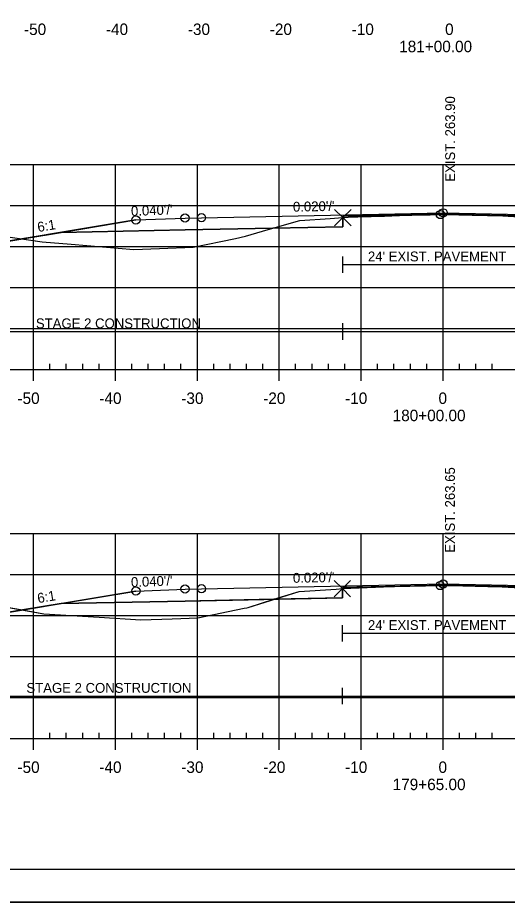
# Model space of a CAD drawing. Extents: x 1365647 to 1367999, y 387113 to 400173.
# Drawn here: x 1365842.2 to 1365901.9, y 388012.7 to 388120.6 of the extents above; entities that cross this region are included whole.
import ezdxf

# ---------------------------------------------------------------- set-up
doc = ezdxf.new("R2010")
doc.units = 0
for name, color, linetype in [('R_Alt Surface', 7, 'Continuous'), ('R_Axis', 7, 'Continuous'), ('R_Axis Annot', 7, 'Continuous'), ('R_Border', 7, 'Continuous'), ('R_Contours', 7, 'Continuous'), ('R_Exist Surface', 7, 'Continuous'), ('R_Fin Surface', 7, 'Continuous'), ('R_Fin Surface Annot', 7, 'Continuous'), ('R_Grid', 7, 'Continuous'), ('R_No Plot', 7, 'Continuous'), ('R_Proposed Const Limits', 7, 'Continuous'), ('R_Water', 7, 'Continuous'), ('R_Xsect Elev', 7, 'Continuous')]:
    doc.layers.add(name, color=color, linetype=linetype)

msp = doc.modelspace()

# ---------------------------------------------------------------- linework, layer by layer
at = {"layer": 'R_Alt Surface'}
for points in [[(1365847.47, 388094.45), (1365862.59, 388094.76), (1365881.85, 388095.14), (1365881.85, 388096.43), (1365894.09, 388096.67), (1365905.63, 388096.44), (1365905.63, 388095.16), (1365925.59, 388094.76), (1365940.72, 388094.45)], [(1365847.47, 388049.19), (1365862.59, 388049.49), (1365881.8, 388049.88), (1365881.8, 388051.16), (1365894.09, 388051.41), (1365905.6, 388051.18), (1365905.6, 388049.89), (1365925.59, 388049.49), (1365940.72, 388049.19)]]:
    msp.add_lwpolyline(points, dxfattribs=at)
at = {"layer": 'R_Axis'}
for p, q in [((1365749.09, 388077.73), (1366039.09, 388077.73)), ((1365844.09, 388076.33), (1365844.09, 388077.73)), ((1365846.09, 388077.73), (1365846.09, 388078.43)), ((1365848.09, 388077.73), (1365848.09, 388078.43)), ((1365850.09, 388077.73), (1365850.09, 388078.43)), ((1365852.09, 388077.73), (1365852.09, 388078.43)), ((1365854.09, 388076.33), (1365854.09, 388077.73)), ((1365856.09, 388077.73), (1365856.09, 388078.43)), ((1365858.09, 388077.73), (1365858.09, 388078.43)), ((1365860.09, 388077.73), (1365860.09, 388078.43)), ((1365862.09, 388077.73), (1365862.09, 388078.43)), ((1365864.09, 388076.33), (1365864.09, 388077.73)), ((1365866.09, 388077.73), (1365866.09, 388078.43)), ((1365868.09, 388077.73), (1365868.09, 388078.43)), ((1365870.09, 388077.73), (1365870.09, 388078.43)), ((1365872.09, 388077.73), (1365872.09, 388078.43)), ((1365874.09, 388076.33), (1365874.09, 388077.73)), ((1365876.09, 388077.73), (1365876.09, 388078.43)), ((1365878.09, 388077.73), (1365878.09, 388078.43)), ((1365880.09, 388077.73), (1365880.09, 388078.43)), ((1365882.09, 388077.73), (1365882.09, 388078.43)), ((1365884.09, 388076.33), (1365884.09, 388077.73)), ((1365886.09, 388077.73), (1365886.09, 388078.43)), ((1365888.09, 388077.73), (1365888.09, 388078.43)), ((1365890.09, 388077.73), (1365890.09, 388078.43)), ((1365892.09, 388077.73), (1365892.09, 388078.43)), ((1365894.09, 388076.33), (1365894.09, 388077.73)), ((1365896.09, 388077.73), (1365896.09, 388078.43)), ((1365898.09, 388077.73), (1365898.09, 388078.43)), ((1365900.09, 388077.73), (1365900.09, 388078.43)), ((1365846.09, 388032.73), (1365846.09, 388033.43)), ((1365848.09, 388032.73), (1365848.09, 388033.43)), ((1365850.09, 388032.73), (1365850.09, 388033.43)), ((1365852.09, 388032.73), (1365852.09, 388033.43)), ((1365856.09, 388032.73), (1365856.09, 388033.43)), ((1365858.09, 388032.73), (1365858.09, 388033.43)), ((1365860.09, 388032.73), (1365860.09, 388033.43)), ((1365862.09, 388032.73), (1365862.09, 388033.43)), ((1365866.09, 388032.73), (1365866.09, 388033.43)), ((1365868.09, 388032.73), (1365868.09, 388033.43)), ((1365870.09, 388032.73), (1365870.09, 388033.43)), ((1365872.09, 388032.73), (1365872.09, 388033.43)), ((1365876.09, 388032.73), (1365876.09, 388033.43)), ((1365878.09, 388032.73), (1365878.09, 388033.43)), ((1365880.09, 388032.73), (1365880.09, 388033.43)), ((1365882.09, 388032.73), (1365882.09, 388033.43)), ((1365886.09, 388032.73), (1365886.09, 388033.43)), ((1365888.09, 388032.73), (1365888.09, 388033.43)), ((1365890.09, 388032.73), (1365890.09, 388033.43)), ((1365892.09, 388032.73), (1365892.09, 388033.43)), ((1365896.09, 388032.73), (1365896.09, 388033.43)), ((1365898.09, 388032.73), (1365898.09, 388033.43)), ((1365900.09, 388032.73), (1365900.09, 388033.43)), ((1365749.09, 388032.73), (1366039.09, 388032.73)), ((1365844.09, 388031.33), (1365844.09, 388032.73)), ((1365854.09, 388031.33), (1365854.09, 388032.73)), ((1365864.09, 388031.33), (1365864.09, 388032.73)), ((1365874.09, 388031.33), (1365874.09, 388032.73)), ((1365884.09, 388031.33), (1365884.09, 388032.73)), ((1365894.09, 388031.33), (1365894.09, 388032.73))]:
    msp.add_line(p, q, dxfattribs=at)
at = {"layer": 'R_Border'}
msp.add_line((1366052.27, 388016.73), (1365736.09, 388016.73), dxfattribs=at)
at = {"layer": 'R_Contours'}
for points in [[(1365873.31, 388094.97), (1365876.58, 388095.9), (1365880.31, 388096.15), (1365881.85, 388096.26), (1365881.85, 388095.14)], [(1365881.85, 388096.26), (1365882.05, 388096.27), (1365882.5, 388096.3), (1365883.7, 388096.34), (1365886.94, 388096.45), (1365888.78, 388096.51), (1365890.29, 388096.54), (1365892.53, 388096.6), (1365893.75, 388096.63), (1365894, 388096.63), (1365894.4, 388096.65), (1365897.62, 388096.57), (1365901.4, 388096.47), (1365903.39, 388096.37), (1365905.63, 388096.26), (1365905.63, 388096.44), (1365894.09, 388096.67), (1365881.85, 388096.43)], [(1365826.79, 388094.91), (1365834.26, 388094.87), (1365839.81, 388094.08), (1365842.68, 388093.66), (1365834.59, 388092.31)], [(1365842.68, 388093.66), (1365845.15, 388093.29), (1365848.67, 388093.01), (1365856.34, 388092.36), (1365859.45, 388092.49), (1365863.56, 388092.65), (1365868.75, 388093.73), (1365869.97, 388093.98), (1365872.74, 388094.81), (1365873.31, 388094.97), (1365862.59, 388094.76), (1365847.47, 388094.45)], [(1365873.44, 388049.71), (1365876.51, 388050.67), (1365881.04, 388050.96), (1365881.8, 388051.01), (1365881.8, 388049.88)], [(1365881.8, 388051.01), (1365881.85, 388051.01), (1365886.83, 388051.21), (1365888.15, 388051.26), (1365891.96, 388051.36), (1365892.91, 388051.38), (1365893.59, 388051.38), (1365893.73, 388051.38), (1365893.92, 388051.38), (1365894.99, 388051.38), (1365898, 388051.29), (1365899.57, 388051.25), (1365901.32, 388051.22), (1365904.17, 388051.05), (1365904.79, 388051.02), (1365905.54, 388050.99), (1365905.6, 388050.98), (1365905.6, 388051.18), (1365894.09, 388051.41), (1365881.8, 388051.16)], [(1365826.18, 388049.85), (1365835.06, 388049.84), (1365838.94, 388049.08), (1365842.76, 388048.41), (1365834.59, 388047.04)], [(1365842.76, 388048.41), (1365845.34, 388047.95), (1365852.12, 388047.54), (1365857.19, 388047.21), (1365861.02, 388047.34), (1365864.15, 388047.43), (1365869.82, 388048.61), (1365870.13, 388048.67), (1365870.28, 388048.72), (1365873.44, 388049.71), (1365862.59, 388049.49), (1365847.47, 388049.19)]]:
    msp.add_lwpolyline(points, close=True, dxfattribs=at)
at = {"layer": 'R_Exist Surface'}
for points in [[(1365839.81, 388094.08), (1365845.15, 388093.29), (1365848.67, 388093.01), (1365856.34, 388092.36), (1365859.45, 388092.49), (1365863.56, 388092.65), (1365868.75, 388093.73), (1365869.97, 388093.98), (1365872.74, 388094.81), (1365876.58, 388095.9), (1365880.31, 388096.15), (1365881.85, 388096.26), (1365882.05, 388096.27), (1365882.5, 388096.3), (1365883.7, 388096.34), (1365886.94, 388096.45), (1365888.78, 388096.51), (1365890.29, 388096.54), (1365892.53, 388096.6), (1365893.75, 388096.63), (1365894, 388096.63), (1365894.4, 388096.65), (1365897.62, 388096.57), (1365901.4, 388096.47), (1365903.39, 388096.37)], [(1365838.94, 388049.08), (1365845.34, 388047.95), (1365852.12, 388047.54), (1365857.19, 388047.21), (1365861.02, 388047.34), (1365864.15, 388047.43), (1365869.82, 388048.61), (1365870.13, 388048.67), (1365870.28, 388048.72), (1365876.51, 388050.67), (1365881.04, 388050.96), (1365881.8, 388051.01), (1365881.85, 388051.01), (1365886.83, 388051.21), (1365888.15, 388051.26), (1365891.96, 388051.36), (1365892.91, 388051.38), (1365893.59, 388051.38), (1365893.73, 388051.38), (1365893.92, 388051.38), (1365894.99, 388051.38), (1365898, 388051.29), (1365899.57, 388051.25), (1365901.32, 388051.22), (1365904.17, 388051.05)]]:
    msp.add_lwpolyline(points, dxfattribs=at)
at = {"layer": 'R_Fin Surface'}
for points in [[(1365826.79, 388094.91), (1365834.59, 388092.31), (1365847.47, 388094.45), (1365856.59, 388095.97), (1365862.59, 388096.21), (1365864.59, 388096.25), (1365894.09, 388096.84), (1365923.59, 388096.25), (1365925.59, 388096.21), (1365931.59, 388095.97), (1365940.72, 388094.45), (1365953.59, 388092.31), (1365958.72, 388094.02)], [(1365856.59, 388095.97), (1365862.59, 388096.21), (1365864.59, 388096.25), (1365894.09, 388096.84), (1365923.59, 388096.25), (1365925.59, 388096.21), (1365931.59, 388095.97)], [(1365826.18, 388049.85), (1365834.59, 388047.04), (1365847.47, 388049.19), (1365856.59, 388050.71), (1365862.59, 388050.95), (1365864.59, 388050.99), (1365894.09, 388051.58), (1365923.59, 388050.99), (1365925.59, 388050.95), (1365931.59, 388050.71), (1365940.72, 388049.19), (1365953.59, 388047.04), (1365959.19, 388048.91)], [(1365856.59, 388050.71), (1365862.59, 388050.95), (1365864.59, 388050.99), (1365894.09, 388051.58), (1365923.59, 388050.99), (1365925.59, 388050.95), (1365931.59, 388050.71)]]:
    msp.add_lwpolyline(points, dxfattribs=at)
at = {"layer": 'R_Grid'}
for p, q in [((1365749.09, 388102.73), (1366039.09, 388102.73)), ((1365844.09, 388077.73), (1365844.09, 388102.73)), ((1365854.09, 388077.73), (1365854.09, 388102.73)), ((1365864.09, 388077.73), (1365864.09, 388102.73)), ((1365874.09, 388077.73), (1365874.09, 388102.73)), ((1365884.09, 388077.73), (1365884.09, 388102.73)), ((1365894.09, 388077.73), (1365894.09, 388102.73)), ((1365749.09, 388097.73), (1366039.09, 388097.73)), ((1365749.09, 388092.73), (1366039.09, 388092.73)), ((1365749.09, 388087.73), (1366039.09, 388087.73)), ((1365749.09, 388082.73), (1366039.09, 388082.73)), ((1365749.09, 388077.73), (1366039.09, 388077.73)), ((1365749.09, 388057.73), (1366039.09, 388057.73)), ((1365844.09, 388032.73), (1365844.09, 388057.73)), ((1365854.09, 388032.73), (1365854.09, 388057.73)), ((1365864.09, 388032.73), (1365864.09, 388057.73)), ((1365874.09, 388032.73), (1365874.09, 388057.73)), ((1365884.09, 388032.73), (1365884.09, 388057.73)), ((1365894.09, 388032.73), (1365894.09, 388057.73)), ((1365749.09, 388052.73), (1366039.09, 388052.73)), ((1365749.09, 388047.73), (1366039.09, 388047.73)), ((1365749.09, 388042.73), (1366039.09, 388042.73)), ((1365749.09, 388037.73), (1366039.09, 388037.73)), ((1365749.09, 388032.73), (1366039.09, 388032.73))]:
    msp.add_line(p, q, dxfattribs=at)
at = {"layer": 'R_No Plot'}
msp.add_line((1365723.69, 388012.75), (1366057.03, 388012.75), dxfattribs=at)
msp.add_lwpolyline([(1365723.69, 388226.09), (1366057.03, 388226.09), (1366057.03, 388012.75), (1365723.69, 388012.75)], close=True, dxfattribs=at)
for points in [[(1365881.85, 388096.26), (1365880.85, 388097.26), (1365881.85, 388096.26), (1365880.85, 388095.26), (1365881.85, 388096.26), (1365882.85, 388095.26), (1365881.85, 388096.26), (1365882.85, 388097.26)], [(1365881.8, 388051.01), (1365880.8, 388052.01), (1365881.8, 388051.01), (1365880.8, 388050.01), (1365881.8, 388051.01), (1365882.8, 388050.01), (1365881.8, 388051.01), (1365882.8, 388052.01)]]:
    msp.add_lwpolyline(points, dxfattribs=at)
for centre in [(1365893.75, 388096.63), (1365894.09, 388096.84), (1365894.09, 388096.84), (1365894.09, 388096.84), (1365894.09, 388096.84), (1365894.09, 388096.84), (1365856.59, 388095.97), (1365856.59, 388095.97), (1365856.59, 388095.97), (1365856.59, 388095.97), (1365856.59, 388095.97), (1365862.59, 388096.21), (1365862.59, 388096.21), (1365862.59, 388096.21), (1365862.59, 388096.21), (1365862.59, 388096.21), (1365864.59, 388096.25), (1365864.59, 388096.25), (1365864.59, 388096.25), (1365864.59, 388096.25), (1365864.59, 388096.25), (1365864.59, 388050.99), (1365864.59, 388050.99), (1365864.59, 388050.99), (1365864.59, 388050.99), (1365864.59, 388050.99), (1365893.73, 388051.38), (1365894.09, 388051.58), (1365894.09, 388051.58), (1365894.09, 388051.58), (1365894.09, 388051.58), (1365894.09, 388051.58), (1365856.59, 388050.71), (1365856.59, 388050.71), (1365856.59, 388050.71), (1365856.59, 388050.71), (1365856.59, 388050.71), (1365862.59, 388050.95), (1365862.59, 388050.95), (1365862.59, 388050.95), (1365862.59, 388050.95), (1365862.59, 388050.95)]:
    msp.add_circle(centre, 0.5, dxfattribs=at)
at = {"layer": 'R_Proposed Const Limits'}
for points in [[(1365856.59, 388095.97), (1365834.59, 388092.31), (1365826.79, 388094.91)], [(1365856.59, 388050.71), (1365834.59, 388047.04), (1365826.18, 388049.85)]]:
    msp.add_lwpolyline(points, dxfattribs=at)
at = {"layer": 'R_Water'}
for p, q in [((1365881.85, 388089.53), (1365881.85, 388091.53)), ((1365881.85, 388090.53), (1365905.63, 388090.53)), ((1365881.85, 388081.37), (1365881.85, 388083.37)), ((1365826.79, 388082.37), (1365881.85, 388082.37)), ((1365881.85, 388082.37), (1365958.72, 388082.37)), ((1365881.8, 388044.57), (1365881.8, 388046.57)), ((1365881.8, 388045.57), (1365905.6, 388045.57)), ((1365881.8, 388036.91), (1365881.8, 388038.91)), ((1365826.13, 388037.91), (1365881.8, 388037.91)), ((1365881.8, 388037.91), (1365959.19, 388037.91))]:
    msp.add_line(p, q, dxfattribs=at)

# ---------------------------------------------------------------- texts
at = {"layer": 'R_Axis Annot'}
for s, p in [('-50', (1365842.93, 388118.53)), ('-40', (1365852.93, 388118.53)), ('-30', (1365862.93, 388118.53)), ('-20', (1365872.93, 388118.53)), ('-10', (1365882.93, 388118.53)), ('0', (1365894.33, 388118.53)), ('181+00.00', (1365888.73, 388116.43)), ('-50', (1365842.13, 388073.53)), ('-40', (1365852.13, 388073.53)), ('-30', (1365862.13, 388073.53)), ('-20', (1365872.13, 388073.53)), ('-10', (1365882.13, 388073.53)), ('0', (1365893.53, 388073.53)), ('180+00.00', (1365887.93, 388071.43)), ('-50', (1365842.13, 388028.53)), ('-40', (1365852.13, 388028.53)), ('-30', (1365862.13, 388028.53)), ('-20', (1365872.13, 388028.53)), ('-10', (1365882.13, 388028.53)), ('0', (1365893.53, 388028.53)), ('179+65.00', (1365887.93, 388026.43))]:
    msp.add_text(s, height=1.4, dxfattribs=at).set_placement(p)
at = {"layer": 'R_Fin Surface Annot'}
for s, rotation, p in [("0.040'/'", 2.2906, (1365856.01, 388096.45)), ("0.020'/'", 1.1458, (1365875.77, 388096.98)), ("0.020'/'", 1.1458, (1365875.77, 388096.98)), ('6:1', 9.4623, (1365844.66, 388094.49)), ("0.040'/'", 2.2906, (1365856.01, 388051.19)), ("0.040'/'", 2.2909, (1365856.01, 388051.19)), ("0.020'/'", 1.1458, (1365875.77, 388051.71)), ("0.020'/'", 1.1458, (1365875.77, 388051.71)), ('6:1', 9.4623, (1365844.66, 388049.23)), ('6:1', 9.4631, (1365844.66, 388049.23))]:
    msp.add_text(s, height=1.2, rotation=rotation, dxfattribs=at).set_placement(p)
at = {"layer": 'R_Water'}
for s, p in [("24' EXIST. PAVEMENT", (1365884.91, 388090.92)), ('STAGE 2 CONSTRUCTION', (1365844.38, 388082.76)), ("24' EXIST. PAVEMENT", (1365884.91, 388045.96)), ('STAGE 2 CONSTRUCTION', (1365843.22, 388038.3))]:
    msp.add_text(s, height=1.2, dxfattribs=at).set_placement(p)
at = {"layer": 'R_Xsect Elev'}
for s, p in [('EXIST. 263.90', (1365895.55, 388100.63)), ('EXIST. 263.65', (1365895.53, 388055.38))]:
    msp.add_text(s, height=1.2, rotation=90, dxfattribs=at).set_placement(p)

doc.saveas('drawing.dxf')
